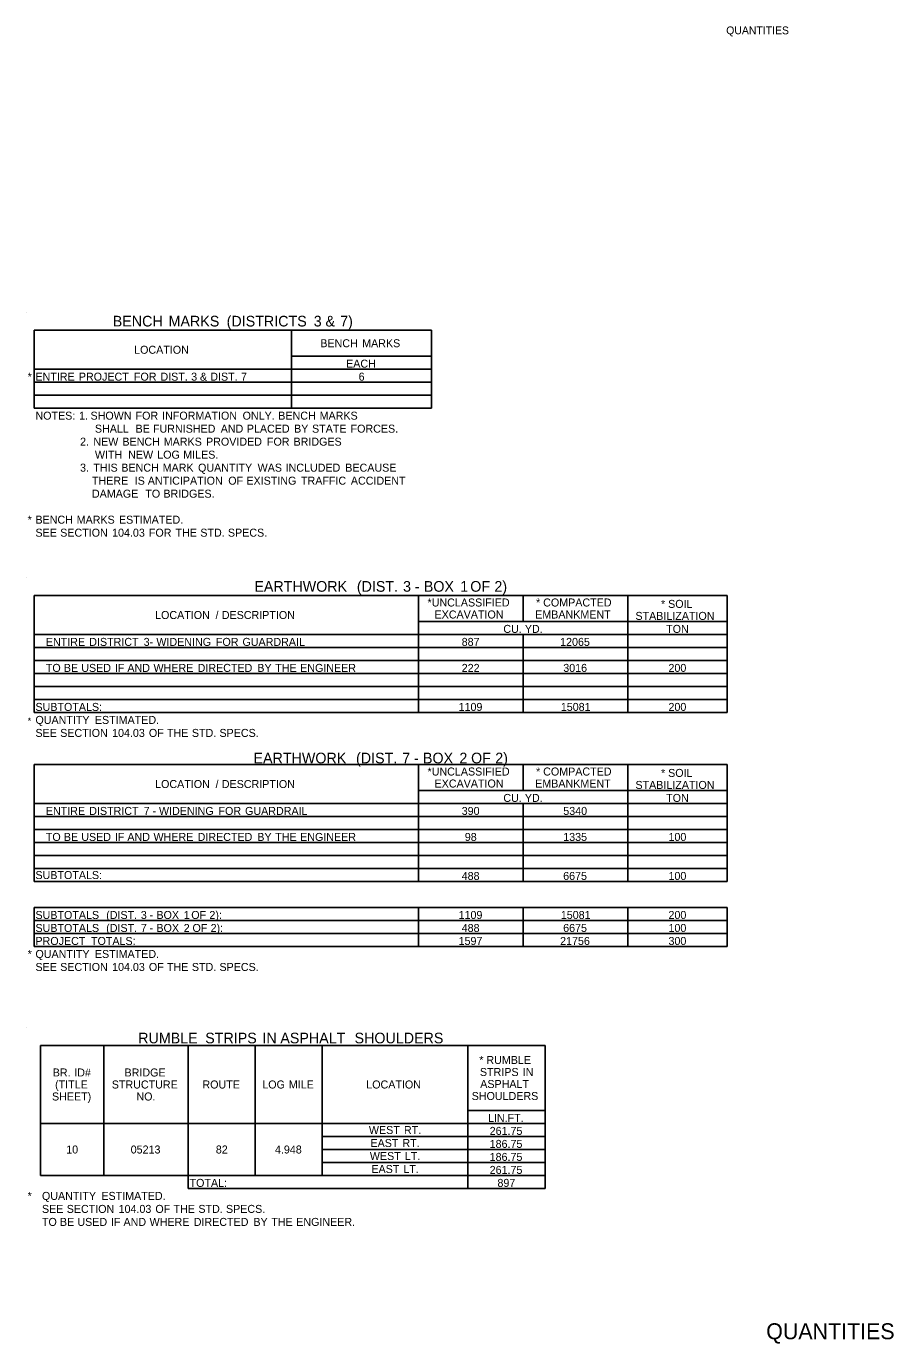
# Model space of a CAD drawing. Extents: x 544478 to 1930787, y -1948294 to 596640.
# Drawn here: x 558438 to 559089, y -1947044 to -1946056 of the extents above; entities that cross this region are included whole.
import ezdxf

# ---------------------------------------------------------------- set-up
doc = ezdxf.new("R2010")
doc.units = 0
for name, color, linetype in [('Default', 7, 'Continuous'), ('R_Border', 7, 'Continuous'), ('R_Border Prem', 7, 'Continuous')]:
    doc.layers.add(name, color=color, linetype=linetype)

msp = doc.modelspace()

# ---------------------------------------------------------------- linework, layer by layer
at = {"layer": 'Default'}
for p, q in [((558438.42, -1946270.68), (558438.42, -1946270.68)), ((558444.27, -1946284.33), (558742.14, -1946284.33)), ((558444.27, -1946342.83), (558444.27, -1946284.33)), ((558444.27, -1946342.83), (558444.27, -1946284.33)), ((558637.32, -1946342.83), (558637.32, -1946284.33)), ((558742.14, -1946342.83), (558742.14, -1946284.33)), ((558637.32, -1946303.83), (558742.14, -1946303.83)), ((558742.14, -1946333.08), (558742.14, -1946303.83)), ((558444.27, -1946313.58), (558742.14, -1946313.58)), ((558637.32, -1946342.83), (558637.32, -1946313.58)), ((558444.27, -1946323.33), (558742.14, -1946323.33)), ((558444.27, -1946333.08), (558742.14, -1946333.08)), ((558444.27, -1946342.83), (558742.14, -1946342.83)), ((558438.42, -1946469.58), (558438.42, -1946469.58)), ((558444.27, -1946483.23), (558963.95, -1946483.23)), ((558444.27, -1946561.23), (558444.27, -1946483.23)), ((558444.27, -1946570.98), (558444.27, -1946483.23)), ((558732.39, -1946570.98), (558732.39, -1946483.23)), ((558810.87, -1946502.73), (558810.87, -1946483.23)), ((558889.36, -1946570.98), (558889.36, -1946483.23)), ((558963.95, -1946570.98), (558963.95, -1946483.23)), ((558963.95, -1946570.98), (558963.95, -1946483.23)), ((558732.39, -1946502.73), (558963.95, -1946502.73)), ((558444.27, -1946512.48), (558963.95, -1946512.48)), ((558732.39, -1946512.48), (558889.36, -1946512.48)), ((558810.87, -1946570.98), (558810.87, -1946512.48)), ((558444.27, -1946522.23), (558963.95, -1946522.23)), ((558444.27, -1946531.98), (558963.95, -1946531.98)), ((558444.27, -1946541.73), (558963.95, -1946541.73)), ((558444.27, -1946551.48), (558963.95, -1946551.48)), ((558444.27, -1946561.23), (558889.36, -1946561.23)), ((558444.27, -1946561.23), (558963.95, -1946561.23)), ((558889.36, -1946561.23), (558963.95, -1946561.23)), ((558444.27, -1946570.98), (558963.95, -1946570.98)), ((558444.27, -1946609.98), (558963.95, -1946609.98)), ((558444.27, -1946687.98), (558444.27, -1946609.98)), ((558444.27, -1946697.73), (558444.27, -1946609.98)), ((558732.39, -1946697.73), (558732.39, -1946609.98)), ((558810.87, -1946629.48), (558810.87, -1946609.98)), ((558889.36, -1946697.73), (558889.36, -1946609.98)), ((558963.95, -1946697.73), (558963.95, -1946609.98)), ((558963.95, -1946697.73), (558963.95, -1946609.98)), ((558732.39, -1946629.48), (558963.95, -1946629.48)), ((558444.27, -1946639.23), (558963.95, -1946639.23)), ((558810.87, -1946697.73), (558810.87, -1946639.23)), ((558444.27, -1946648.98), (558963.95, -1946648.98)), ((558444.27, -1946658.73), (558963.95, -1946658.73)), ((558444.27, -1946668.48), (558963.95, -1946668.48)), ((558444.27, -1946678.23), (558963.95, -1946678.23)), ((558444.27, -1946687.98), (558889.36, -1946687.98)), ((558444.27, -1946687.98), (558963.95, -1946687.98)), ((558889.36, -1946687.98), (558963.95, -1946687.98)), ((558444.27, -1946697.73), (558963.95, -1946697.73)), ((558444.27, -1946717.23), (558963.95, -1946717.23)), ((558444.27, -1946717.23), (558963.95, -1946717.23)), ((558444.27, -1946746.48), (558444.27, -1946717.23)), ((558444.27, -1946746.48), (558444.27, -1946717.23)), ((558732.39, -1946746.48), (558732.39, -1946717.23)), ((558810.87, -1946746.48), (558810.87, -1946717.23)), ((558889.36, -1946746.48), (558889.36, -1946717.23)), ((558963.95, -1946746.48), (558963.95, -1946717.23)), ((558963.95, -1946746.48), (558963.95, -1946717.23)), ((558444.27, -1946726.98), (558963.95, -1946726.98)), ((558444.27, -1946736.73), (558963.95, -1946736.73)), ((558444.27, -1946746.48), (558963.95, -1946746.48)), ((558438.42, -1946807.01), (558438.42, -1946807.01)), ((558449.15, -1946820.66), (558827.45, -1946820.66)), ((558449.15, -1946820.66), (558827.45, -1946820.66)), ((558449.15, -1946918.16), (558449.15, -1946820.66)), ((558449.15, -1946918.16), (558449.15, -1946820.66)), ((558496.44, -1946918.16), (558496.44, -1946820.66)), ((558559.81, -1946927.91), (558559.81, -1946820.66)), ((558610.02, -1946918.16), (558610.02, -1946820.66)), ((558660.24, -1946879.16), (558660.24, -1946820.66)), ((558660.24, -1946918.16), (558660.24, -1946820.66)), ((558769.44, -1946927.91), (558769.44, -1946820.66)), ((558827.45, -1946927.91), (558827.45, -1946820.66)), ((558769.44, -1946869.41), (558827.45, -1946869.41)), ((558449.15, -1946879.16), (558827.45, -1946879.16)), ((558660.24, -1946888.91), (558827.45, -1946888.91)), ((558660.24, -1946898.66), (558769.44, -1946898.66)), ((558660.24, -1946898.66), (558827.45, -1946898.66)), ((558660.24, -1946908.41), (558827.45, -1946908.41)), ((558449.15, -1946918.16), (558827.45, -1946918.16)), ((558559.81, -1946918.16), (558660.24, -1946918.16)), ((558559.81, -1946927.91), (558559.81, -1946918.16)), ((558660.24, -1946918.16), (558827.45, -1946918.16)), ((558559.81, -1946927.91), (558827.45, -1946927.91))]:
    msp.add_line(p, q, dxfattribs=at)

# ---------------------------------------------------------------- texts
for s, height, p in [('BENCH', 8, (558503.21, -1946281.51)), (' MARKS', 8, (558542.1, -1946281.51)), (' (DISTRICTS', 8, (558585.64, -1946281.51)), (' 3', 8, (558650.92, -1946281.51)), (' &', 8, (558659.75, -1946281.51)), (' 7)', 8, (558670.74, -1946281.51)), ('BENCH', 6, (558658.82, -1946297.08)), (' MARKS', 6, (558687.99, -1946297.08)), ('LOCATION', 6, (558519.25, -1946301.96)), ('EACH', 6, (558678.17, -1946312.38)), ('*', 6, (558439.4, -1946322.13)), ('ENTIRE', 6, (558445.25, -1946322.13)), (' PROJECT', 6, (558475.55, -1946322.13)), (' FOR', 6, (558516.84, -1946322.13)), (' DIST.', 6, (558536.75, -1946322.13)), (' 3', 6, (558559.77, -1946322.13)), (' &', 6, (558566.38, -1946322.13)), (' DIST.', 6, (558574.11, -1946322.13)), (' 7', 6, (558597.13, -1946322.13)), ('6', 6, (558687.55, -1946322.13)), ('NOTES:', 6, (558445.25, -1946351.38)), (' 1.', 6, (558475.73, -1946351.38)), (' SHOWN', 6, (558484.31, -1946351.38)), (' FOR', 6, (558518.09, -1946351.38)), (' INFORMATION', 6, (558538, -1946351.38)), (' ONLY.', 6, (558598.33, -1946351.38)), (' BENCH', 6, (558625.08, -1946351.38)), (' MARKS', 6, (558656.08, -1946351.38)), ('                    SHALL', 6, (558445.25, -1946361.13)), (' BE', 6, (558518.07, -1946361.13)), (' FURNISHED', 6, (558531.13, -1946361.13)), (' AND', 6, (558581.92, -1946361.13)), (' PLACED', 6, (558601.5, -1946361.13)), (' BY', 6, (558636.93, -1946361.13)), (' STATE', 6, (558650.38, -1946361.13)), (' FORCES.', 6, (558679.29, -1946361.13)), ('               2.', 6, (558445.25, -1946370.88)), (' NEW', 6, (558486.42, -1946370.88)), (' BENCH', 6, (558508.21, -1946370.88)), (' MARKS', 6, (558539.21, -1946370.88)), (' PROVIDED', 6, (558570.92, -1946370.88)), (' FOR', 6, (558616.59, -1946370.88)), (' BRIDGES', 6, (558636.5, -1946370.88)), ('                    WITH', 6, (558445.25, -1946380.63)), (' NEW', 6, (558512.54, -1946380.63)), (' LOG', 6, (558534.33, -1946380.63)), (' MILES.', 6, (558553.84, -1946380.63)), ('               3.', 6, (558445.25, -1946390.38)), (' THIS', 6, (558486.42, -1946390.38)), (' BENCH', 6, (558507.41, -1946390.38)), (' MARK', 6, (558538.41, -1946390.38)), (' QUANTITY', 6, (558564.94, -1946390.38)), (' WAS', 6, (558609.59, -1946390.38)), (' INCLUDED', 6, (558630.58, -1946390.38)), (' BECAUSE', 6, (558675.32, -1946390.38)), ('                   THERE', 6, (558445.25, -1946400.13)), (' IS', 6, (558517.45, -1946400.13)), (' ANTICIPATION', 6, (558527.25, -1946400.13)), (' OF', 6, (558587.59, -1946400.13)), (' EXISTING', 6, (558601.18, -1946400.13)), (' TRAFFIC', 6, (558642.11, -1946400.13)), (' ACCIDENT', 6, (558679.5, -1946400.13)), ('                   DAMAGE', 6, (558445.25, -1946409.88)), (' TO', 6, (558525.37, -1946409.88)), (' BRIDGES.', 6, (558538.96, -1946409.88)), ('*', 6, (558439.4, -1946429.38)), ('BENCH', 6, (558445.25, -1946429.38)), (' MARKS', 6, (558473.92, -1946429.38)), (' ESTIMATED.', 6, (558505.63, -1946429.38)), ('SEE', 6, (558445.25, -1946439.13)), (' SECTION', 6, (558461.58, -1946439.13)), (' 104.03', 6, (558500.49, -1946439.13)), (' FOR', 6, (558528.06, -1946439.13)), (' THE', 6, (558547.98, -1946439.13)), (' STD.', 6, (558566.63, -1946439.13)), (' SPECS.', 6, (558587.32, -1946439.13)), ('EARTHWORK', 8, (558609.38, -1946480.41)), (' (DIST.', 8, (558683.25, -1946480.41)), (' 3', 8, (558717.88, -1946480.41)), (' -', 8, (558726.71, -1946480.41)), (' BOX', 8, (558733.46, -1946480.41)), (' 1', 8, (558760.77, -1946480.41)), (' OF', 8, (558768.28, -1946480.41)), (' 2)', 8, (558786.39, -1946480.41)), ('*UNCLASSIFIED', 6, (558739.23, -1946491.48)), ('*', 6, (558820.6, -1946491.48)), (' COMPACTED', 6, (558823.69, -1946491.48)), ('*', 6, (558914.29, -1946492.53)), (' SOIL', 6, (558917.38, -1946492.53)), ('LOCATION', 6, (558534.97, -1946500.86)), (' /', 6, (558578.07, -1946500.86)), (' DESCRIPTION', 6, (558582.74, -1946500.86)), ('EXCAVATION', 6, (558744.48, -1946500.48)), ('EMBANKMENT', 6, (558819.93, -1946500.48)), ('STABILIZATION', 6, (558895.09, -1946501.53)), ('CU.', 6, (558796.08, -1946511.28)), (' YD.', 6, (558809.94, -1946511.28)), ('TON', 6, (558918.14, -1946511.28)), ('ENTIRE', 6, (558453.05, -1946521.03)), (' DISTRICT', 6, (558483.35, -1946521.03)), (' 3-', 6, (558524.16, -1946521.03)), (' WIDENING', 6, (558533.68, -1946521.03)), (' FOR', 6, (558578.33, -1946521.03)), (' GUARDRAIL', 6, (558598.24, -1946521.03)), ('887', 6, (558764.83, -1946521.03)), ('12065', 6, (558838.63, -1946521.03)), ('TO', 6, (558453.05, -1946540.53)), (' BE', 6, (558464.32, -1946540.53)), (' USED', 6, (558477.38, -1946540.53)), (' IF', 6, (558502.56, -1946540.53)), (' AND', 6, (558511.95, -1946540.53)), (' WHERE', 6, (558531.53, -1946540.53)), (' DIRECTED', 6, (558564.62, -1946540.53)), (' BY', 6, (558609.36, -1946540.53)), (' THE', 6, (558622.8, -1946540.53)), (' ENGINEER', 6, (558641.45, -1946540.53)), ('222', 6, (558764.86, -1946540.53)), ('3016', 6, (558840.99, -1946540.53)), ('200', 6, (558919.87, -1946540.53)), ('SUBTOTALS:', 6, (558445.25, -1946569.78)), ('1109', 6, (558762.5, -1946569.78)), ('15081', 6, (558839.15, -1946569.78)), ('200', 6, (558919.87, -1946569.78)), ('*', 5, (558439.4, -1946579.73)), ('QUANTITY', 6, (558445.25, -1946579.53)), (' ESTIMATED.', 6, (558487.57, -1946579.53)), ('SEE', 6, (558445.25, -1946589.28)), (' SECTION', 6, (558461.58, -1946589.28)), (' 104.03', 6, (558500.49, -1946589.28)), (' OF', 6, (558528.06, -1946589.28)), (' THE', 6, (558541.65, -1946589.28)), (' STD.', 6, (558560.3, -1946589.28)), (' SPECS.', 6, (558580.99, -1946589.28)), ('EARTHWORK', 8, (558608.76, -1946609.11)), (' (DIST.', 8, (558682.64, -1946609.11)), (' 7', 8, (558717.26, -1946609.11)), (' -', 8, (558726.08, -1946609.11)), (' BOX', 8, (558732.82, -1946609.11)), (' 2', 8, (558760.14, -1946609.11)), (' OF', 8, (558768.9, -1946609.11)), (' 2)', 8, (558787.01, -1946609.11)), ('*UNCLASSIFIED', 6, (558739.23, -1946618.23)), ('*', 6, (558820.6, -1946618.23)), (' COMPACTED', 6, (558823.69, -1946618.23)), ('*', 6, (558914.29, -1946619.28)), (' SOIL', 6, (558917.38, -1946619.28)), ('LOCATION', 6, (558534.97, -1946627.61)), (' /', 6, (558578.07, -1946627.61)), (' DESCRIPTION', 6, (558582.74, -1946627.61)), ('EXCAVATION', 6, (558744.48, -1946627.23)), ('EMBANKMENT', 6, (558819.93, -1946627.23)), ('STABILIZATION', 6, (558895.09, -1946628.28)), ('CU.', 6, (558796.08, -1946638.03)), (' YD.', 6, (558809.94, -1946638.03)), ('TON', 6, (558918.14, -1946638.03)), ('ENTIRE', 6, (558453.05, -1946647.78)), (' DISTRICT', 6, (558483.35, -1946647.78)), (' 7', 6, (558524.16, -1946647.78)), (' -', 6, (558530.77, -1946647.78)), (' WIDENING', 6, (558535.63, -1946647.78)), (' FOR', 6, (558580.27, -1946647.78)), (' GUARDRAIL', 6, (558600.19, -1946647.78)), ('390', 6, (558764.84, -1946647.78)), ('5340', 6, (558841, -1946647.78)), ('TO', 6, (558453.05, -1946667.28)), (' BE', 6, (558464.32, -1946667.28)), (' USED', 6, (558477.38, -1946667.28)), (' IF', 6, (558502.56, -1946667.28)), (' AND', 6, (558511.95, -1946667.28)), (' WHERE', 6, (558531.53, -1946667.28)), (' DIRECTED', 6, (558564.62, -1946667.28)), (' BY', 6, (558609.36, -1946667.28)), (' THE', 6, (558622.8, -1946667.28)), (' ENGINEER', 6, (558641.45, -1946667.28)), ('98', 6, (558767.16, -1946667.28)), ('1335', 6, (558840.96, -1946667.28)), ('100', 6, (558919.87, -1946667.28)), ('SUBTOTALS:', 6, (558445.25, -1946695.86)), ('488', 6, (558764.83, -1946696.53)), ('6675', 6, (558840.92, -1946696.53)), ('100', 6, (558919.87, -1946696.53)), ('SUBTOTALS', 6, (558445.25, -1946725.78)), (' (DIST.', 6, (558496.07, -1946725.78)), (' 3', 6, (558522.04, -1946725.78)), (' -', 6, (558528.67, -1946725.78)), (' BOX', 6, (558533.73, -1946725.78)), (' 1', 6, (558554.21, -1946725.78)), (' OF', 6, (558559.84, -1946725.78)), (' 2):', 6, (558573.43, -1946725.78)), ('1109', 6, (558762.5, -1946725.78)), ('15081', 6, (558839.15, -1946725.78)), ('200', 6, (558919.87, -1946725.78)), ('SUBTOTALS', 6, (558445.25, -1946735.53)), (' (DIST.', 6, (558496.07, -1946735.53)), (' 7', 6, (558522.04, -1946735.53)), (' -', 6, (558528.66, -1946735.53)), (' BOX', 6, (558533.72, -1946735.53)), (' 2', 6, (558554.2, -1946735.53)), (' OF', 6, (558560.77, -1946735.53)), (' 2):', 6, (558574.35, -1946735.53)), ('488', 6, (558764.83, -1946735.53)), ('6675', 6, (558840.92, -1946735.53)), ('100', 6, (558919.87, -1946735.53)), ('PROJECT', 6, (558445.25, -1946745.28)), (' TOTALS:', 6, (558484.67, -1946745.28)), ('1597', 6, (558762.5, -1946745.28)), ('21756', 6, (558838.62, -1946745.28)), ('300', 6, (558919.87, -1946745.28)), ('*', 6, (558439.4, -1946755.03)), ('QUANTITY', 6, (558445.25, -1946755.03)), (' ESTIMATED.', 6, (558487.57, -1946755.03)), ('SEE', 6, (558445.25, -1946764.78)), (' SECTION', 6, (558461.58, -1946764.78)), (' 104.03', 6, (558500.49, -1946764.78)), (' OF', 6, (558528.06, -1946764.78)), (' THE', 6, (558541.65, -1946764.78)), (' STD.', 6, (558560.3, -1946764.78)), (' SPECS.', 6, (558580.99, -1946764.78)), ('RUMBLE', 8, (558522.3, -1946819.06)), (' STRIPS', 8, (558569.57, -1946819.06)), (' IN', 8, (558612.5, -1946819.06)), (' ASPHALT', 8, (558625.88, -1946819.06)), (' SHOULDERS', 8, (558681.55, -1946819.06)), ('*', 6, (558778.01, -1946834.53)), (' RUMBLE', 6, (558781.1, -1946834.53)), ('BR.', 6, (558458.22, -1946843.91)), (' ID#', 6, (558472.09, -1946843.91)), ('BRIDGE', 6, (558512.03, -1946843.91)), ('STRIPS', 6, (558778.49, -1946843.53)), (' IN', 6, (558808.36, -1946843.53)), ('(TITLE', 6, (558459.96, -1946852.91)), ('STRUCTURE', 6, (558502.48, -1946852.91)), ('ROUTE', 6, (558570.45, -1946852.91)), ('LOG', 6, (558615.33, -1946852.91)), (' MILE', 6, (558632.99, -1946852.91)), ('LOCATION', 6, (558693.28, -1946852.91)), ('ASPHALT', 6, (558778.73, -1946852.53)), ('SHEET)', 6, (558457.64, -1946861.91)), ('NO.', 6, (558520.96, -1946861.91)), ('SHOULDERS', 6, (558772.33, -1946861.53)), ('LIN.FT.', 6, (558784.53, -1946877.96)), ('WEST', 6, (558695.26, -1946887.03)), (' RT.', 6, (558719.31, -1946887.03)), ('261.75', 6, (558785.8, -1946887.71)), ('EAST', 6, (558696.42, -1946896.78)), (' RT.', 6, (558718.15, -1946896.78)), ('186.75', 6, (558785.8, -1946897.46)), ('10', 6, (558468.33, -1946901.66)), ('05213', 6, (558516.66, -1946901.66)), ('82', 6, (558580.48, -1946901.66)), ('4.948', 6, (558624.83, -1946901.66)), ('WEST', 6, (558695.96, -1946906.53)), (' LT.', 6, (558720.01, -1946906.53)), ('186.75', 6, (558785.8, -1946907.21)), ('EAST', 6, (558697.12, -1946916.28)), (' LT.', 6, (558718.85, -1946916.28)), ('261.75', 6, (558785.8, -1946916.96)), ('TOTAL:', 6, (558560.79, -1946926.71)), ('897', 6, (558791.64, -1946926.71)), ('*', 6, (558439.4, -1946936.46)), ('QUANTITY', 6, (558450.12, -1946936.46)), (' ESTIMATED.', 6, (558492.45, -1946936.46)), ('SEE', 6, (558450.12, -1946946.21)), (' SECTION', 6, (558466.45, -1946946.21)), (' 104.03', 6, (558505.36, -1946946.21)), (' OF', 6, (558532.94, -1946946.21)), (' THE', 6, (558546.53, -1946946.21)), (' STD.', 6, (558565.18, -1946946.21)), (' SPECS.', 6, (558585.87, -1946946.21)), ('TO', 6, (558450.12, -1946955.96)), (' BE', 6, (558461.39, -1946955.96)), (' USED', 6, (558474.46, -1946955.96)), (' IF', 6, (558499.63, -1946955.96)), (' AND', 6, (558509.03, -1946955.96)), (' WHERE', 6, (558528.61, -1946955.96)), (' DIRECTED', 6, (558561.7, -1946955.96)), (' BY', 6, (558606.43, -1946955.96)), (' THE', 6, (558619.88, -1946955.96)), (' ENGINEER.', 6, (558638.53, -1946955.96))]:
    msp.add_text(s, height=height, dxfattribs=at).set_placement(p)
at = {"layer": 'R_Border'}
msp.add_text('QUANTITIES', height=12, rotation=360, dxfattribs=at).set_placement((558993.14, -1947040.95))
at = {"layer": 'R_Border Prem'}
msp.add_text('QUANTITIES', height=5.862, rotation=360, dxfattribs=at).set_placement((558963.16, -1946062.39))

doc.saveas('drawing.dxf')
